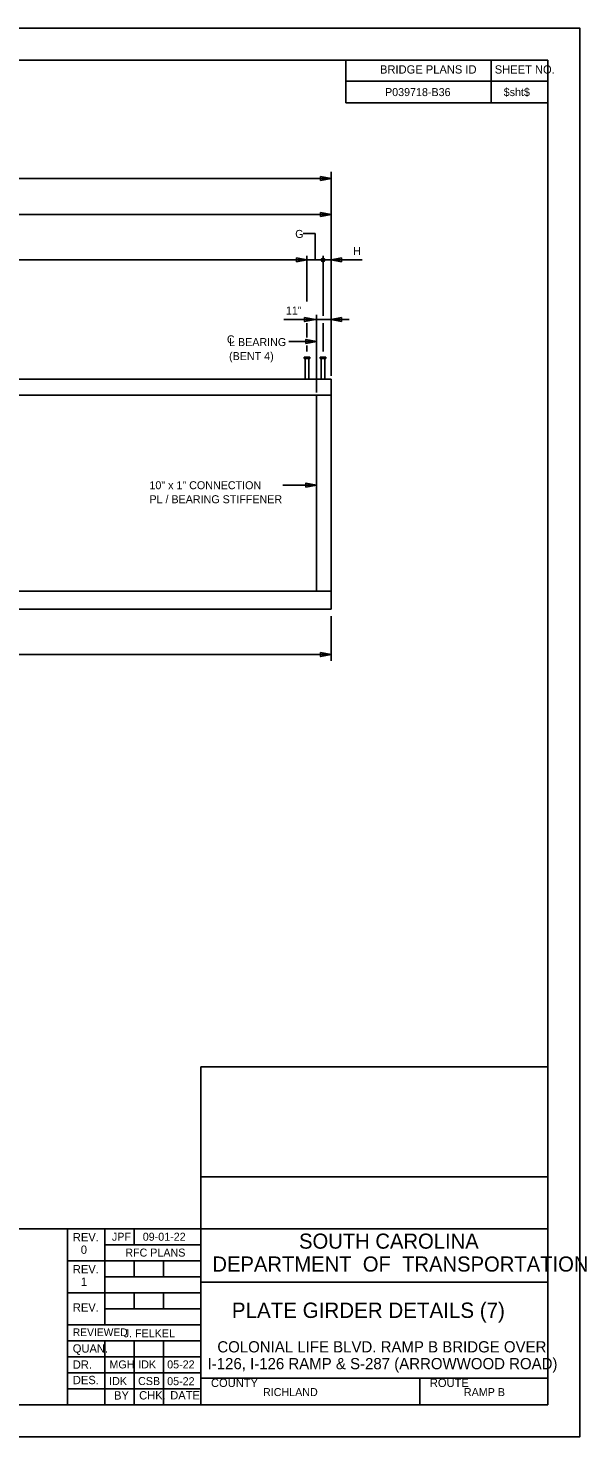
# Model space of a CAD drawing. Extents: x -305 to -161, y -187 to -99.
# Drawn here: x -195.6 to -160.8, y -187.5 to -99.5 of the extents above; entities that cross this region are included whole.
import ezdxf

# ---------------------------------------------------------------- set-up
doc = ezdxf.new("R2010")
doc.units = 0
for name, color, linetype in [('BR_AUTO DIMENSION', 7, 'Continuous'), ('BR_BORDER LINES', 7, 'Continuous'), ('BR_CENTER LINES', 7, 'Continuous'), ('BR_STRUCTURAL STEEL', 7, 'Continuous'), ('BR_TEXT', 7, 'Continuous'), ('Default', 7, 'Continuous'), ('Level 31', 7, 'Continuous')]:
    doc.layers.add(name, color=color, linetype=linetype)

msp = doc.modelspace()

# ---------------------------------------------------------------- linework, layer by layer
at = {"layer": 'BR_AUTO DIMENSION'}
for p, q in [((-284.971, -108.876), (-176.721, -108.876)), ((-176.721, -121.218), (-176.721, -108.463)), ((-284.971, -111.134), (-176.721, -111.134)), ((-178.221, -113.971), (-283.471, -113.971)), ((-178.221, -116.554), (-178.221, -113.71)), ((-174.768, -113.971), (-178.221, -113.971)), ((-177.221, -117.468), (-177.221, -113.71)), ((-179.677, -117.696), (-175.581, -117.696)), ((-178.221, -118.804), (-178.221, -117.923)), ((-177.221, -119.685), (-177.221, -117.923)), ((-177.638, -119.058), (-179.361, -119.058)), ((-178.221, -119.685), (-178.221, -119.322)), ((-177.638, -128.037), (-179.72, -128.037)), ((-176.721, -136.215), (-176.721, -139.018)), ((-284.971, -138.617), (-176.721, -138.617))]:
    msp.add_line(p, q, dxfattribs=at)
for points in [[(-177.371, -108.751), (-176.721, -108.876), (-177.371, -109.001)], [(-177.371, -111.259), (-176.721, -111.134), (-177.371, -111.009)], [(-178.871, -114.096), (-178.221, -113.971), (-178.871, -113.846)], [(-176.071, -114.096), (-176.721, -113.971), (-176.071, -113.846)], [(-178.371, -117.571), (-177.721, -117.696), (-178.371, -117.821)], [(-176.071, -117.821), (-176.721, -117.696), (-176.071, -117.571)], [(-178.288, -119.183), (-177.638, -119.058), (-178.288, -118.933)], [(-178.288, -128.162), (-177.638, -128.037), (-178.288, -127.912)], [(-177.371, -138.492), (-176.721, -138.617), (-177.371, -138.742)]]:
    msp.add_lwpolyline(points, close=True, dxfattribs=at)
msp.add_lwpolyline([(-177.721, -113.971), (-177.721, -112.325), (-178.461, -112.325)], dxfattribs=at)
msp.add_circle((-177.221, -113.971), 0.111, dxfattribs=at)
at = {"layer": 'BR_BORDER LINES'}
for p, q in [((-163.178, -101.489), (-297.843, -101.489)), ((-175.788, -104.156), (-175.788, -101.489)), ((-166.722, -104.156), (-166.722, -101.489)), ((-163.178, -185.489), (-163.178, -101.489)), ((-175.788, -102.808), (-163.178, -102.808)), ((-166.722, -102.808), (-163.178, -102.808)), ((-163.178, -104.156), (-175.788, -104.156)), ((-184.846, -185.489), (-184.846, -164.383)), ((-184.846, -164.383), (-163.178, -164.383)), ((-184.845, -171.242), (-163.178, -171.242)), ((-214.64, -174.489), (-193.18, -174.489)), ((-193.18, -185.489), (-193.18, -174.489)), ((-193.18, -174.489), (-163.178, -174.489)), ((-190.846, -174.489), (-190.846, -180.489)), ((-189.013, -175.489), (-189.013, -174.489)), ((-190.846, -175.489), (-184.846, -175.489)), ((-193.18, -176.489), (-184.846, -176.489)), ((-189.013, -177.489), (-189.013, -176.489)), ((-187.179, -177.489), (-187.179, -176.489)), ((-190.846, -177.489), (-184.846, -177.489)), ((-193.18, -178.489), (-184.846, -178.489)), ((-189.013, -179.489), (-189.013, -178.489)), ((-187.179, -179.489), (-187.179, -178.489)), ((-184.846, -177.822), (-184.846, -177.822)), ((-184.846, -177.823), (-163.178, -177.823)), ((-190.846, -179.489), (-184.846, -179.489)), ((-193.18, -180.489), (-184.846, -180.489)), ((-193.18, -181.489), (-184.846, -181.489)), ((-190.846, -181.489), (-190.846, -185.489)), ((-189.013, -181.489), (-189.013, -185.489)), ((-187.179, -181.489), (-187.179, -185.489)), ((-193.18, -182.489), (-184.846, -182.489)), ((-193.18, -183.489), (-184.846, -183.489)), ((-184.846, -183.823), (-163.178, -183.823)), ((-184.456, -183.823), (-163.178, -183.823)), ((-171.179, -185.489), (-171.179, -183.823)), ((-193.18, -184.489), (-184.846, -184.489)), ((-297.843, -185.489), (-163.178, -185.489))]:
    msp.add_line(p, q, dxfattribs=at)
at = {"layer": 'BR_CENTER LINES'}
msp.add_line((-177.638, -117.387), (-177.638, -122.256), dxfattribs=at)
at = {"layer": 'BR_STRUCTURAL STEEL'}
for p, q in [((-284.971, -121.412), (-176.721, -121.412)), ((-176.721, -121.412), (-176.721, -122.412)), ((-284.971, -122.412), (-176.721, -122.412)), ((-177.638, -122.412), (-177.638, -134.662)), ((-176.721, -122.412), (-176.721, -134.662)), ((-284.971, -134.662), (-176.721, -134.662)), ((-176.721, -134.662), (-176.721, -135.787)), ((-284.971, -135.787), (-176.721, -135.787))]:
    msp.add_line(p, q, dxfattribs=at)
at = {"layer": 'Default'}
for p, q in [((-178.393, -120.037), (-178.393, -120.131)), ((-178.393, -120.037), (-178.049, -120.037)), ((-178.393, -120.131), (-178.049, -120.131)), ((-178.33, -120.131), (-178.33, -121.412)), ((-178.112, -120.131), (-178.112, -121.412)), ((-178.049, -120.037), (-178.049, -120.131)), ((-177.393, -120.037), (-177.393, -120.131)), ((-177.393, -120.037), (-177.049, -120.037)), ((-177.393, -120.131), (-177.049, -120.131)), ((-177.33, -120.131), (-177.33, -121.412)), ((-177.112, -120.131), (-177.112, -121.412)), ((-177.049, -120.037), (-177.049, -120.131))]:
    msp.add_line(p, q, dxfattribs=at)
at = {"layer": 'Level 31'}
msp.add_line((-174.011, -179.583), (-174.011, -179.583), dxfattribs=at)
msp.add_lwpolyline([(-305.176, -187.489), (-161.176, -187.489), (-161.176, -99.489), (-305.176, -99.489)], close=True, dxfattribs=at)

# ---------------------------------------------------------------- texts
at = {"layer": 'BR_AUTO DIMENSION'}
for s, p in [('G', (-178.957, -112.593)), ('H', (-175.34, -113.652)), ('11"', (-179.54, -117.377))]:
    msp.add_text(s, height=0.5, rotation=360, dxfattribs=at).set_placement(p)
at = {"layer": 'BR_TEXT'}
for s, height, p in [('BRIDGE PLANS ID', 0.52, (-173.663, -102.327)), ('SHEET NO.', 0.52, (-166.499, -102.327)), ('P039718-B36', 0.5, (-173.348, -103.732)), ('$sht$', 0.5, (-165.939, -103.732)), ('REV.', 0.52, (-192.841, -175.277)), ('JPF', 0.5, (-190.4, -175.239)), ('09-01-22', 0.5, (-188.475, -175.239)), ('SOUTH CAROLINA', 0.94348, (-178.718, -175.735)), ('0', 0.52, (-192.345, -176.057)), ('RFC PLANS', 0.5, (-189.566, -176.229)), ('REV.', 0.52, (-192.841, -177.277)), ('DEPARTMENT  OF  TRANSPORTATION', 0.94348, (-184.129, -177.166)), ('1', 0.52, (-192.337, -178.057)), ('REV.', 0.52, (-192.841, -179.667)), ('PLATE GIRDER DETAILS (7)', 0.96, (-182.913, -180.063)), ('REVIEWED', 0.48, (-192.843, -181.195)), ('J. FELKEL', 0.5, (-189.664, -181.272)), ('QUAN.', 0.52, (-192.846, -182.229)), ('COLONIAL LIFE BLVD. RAMP B BRIDGE OVER', 0.7, (-183.82, -182.216)), ('DR.', 0.52, (-192.845, -183.235)), ('MGH', 0.5, (-190.556, -183.215)), ('IDK', 0.5, (-188.758, -183.215)), ('05-22', 0.5, (-186.951, -183.215)), ('I-126, I-126 RAMP & S-287 (ARROWWOOD ROAD) ', 0.7, (-184.429, -183.266)), ('DES.', 0.52, (-192.841, -184.2)), ('IDK', 0.5, (-190.574, -184.254)), ('CSB', 0.5, (-188.767, -184.254)), ('05-22', 0.5, (-186.951, -184.263)), ('COUNTY', 0.52, (-184.217, -184.376)), ('ROUTE', 0.52, (-170.55, -184.376)), ('BY', 0.52, (-190.265, -185.161)), ('CHK.', 0.52, (-188.701, -185.156)), ('DATE', 0.52, (-186.761, -185.156)), ('RICHLAND', 0.5, (-180.968, -184.944)), ('RAMP B', 0.5, (-168.424, -184.944))]:
    msp.add_text(s, height=height, dxfattribs=at).set_placement(p)
for s, p in [('C', (-183.221, -119.181)), ('L BEARING', (-183.086, -119.348)), ('(BENT 4)', (-183.086, -120.223)), ('10" x 1" CONNECTION ', (-188.059, -128.293)), ('PL / BEARING STIFFENER', (-188.059, -129.168))]:
    msp.add_text(s, height=0.5, rotation=360, dxfattribs=at).set_placement(p)

doc.saveas('drawing.dxf')
